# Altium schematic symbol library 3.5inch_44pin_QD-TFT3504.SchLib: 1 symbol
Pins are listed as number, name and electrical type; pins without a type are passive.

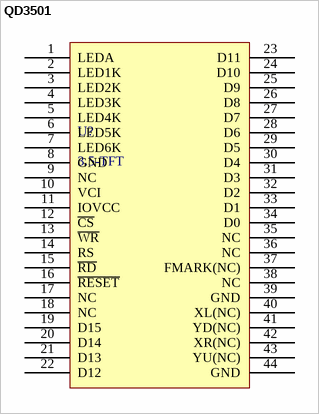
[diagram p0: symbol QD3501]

## QD3501
designator U?, comment 3.5-TFT
3.5inch TFT LCD
pins: 1 LEDA, 2 LED1K, 3 LED2K, 4 LED3K, 5 LED4K, 6 LED5K, 7 LED6K, 8 GND, 9 NC, 10 VCI, 11 IOVCC, 12 ~{CS}, 13 ~{WR}, 14 RS, 15 ~{RD}, 16 ~{RESET}, 17 NC, 18 NC, 19 D15, 20 D14, 21 D13, 22 D12, 23 D11, 24 D10, 25 D9, 26 D8, 27 D7, 28 D6, 29 D5, 30 D4, 31 D3, 32 D2, 33 D1, 34 D0, 35 NC, 36 NC, 37 FMARK(NC), 38 NC, 39 GND, 40 XL(NC), 41 YD(NC), 42 XR(NC), 43 YU(NC), 44 GND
